// Mitsubishi GX Works2 project: 21.8电机点动互锁（复杂）   PLC: FX3U/FX3UC

PROGRAM MAIN
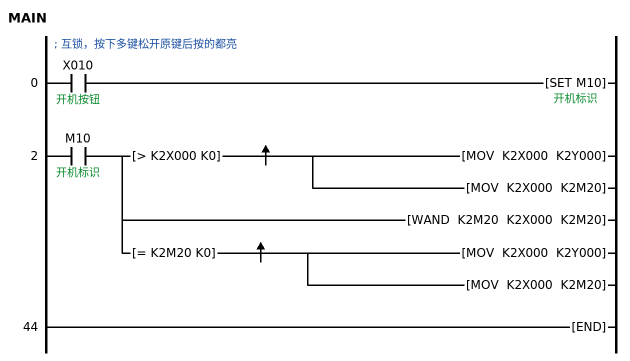
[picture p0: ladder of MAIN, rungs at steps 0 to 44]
; 互锁，按下多键松开原键后按的都亮
0     LD      X010  ; 开机按钮
      SET     M10  ; 开机标识
2     LD      M10  ; 开机标识
      MPS
      AND>    K2X000 K0  ; 启动按钮
      MEP
      MOV     K2X000 K2Y000  ; 电机
        [note] 按下K2X0时执行K2Y0
      MOV     K2X000 K2M20  ; 记录按键情况
        [note] 将K2X0按下的情况记录
      MPP
      WAND    K2M20 K2X000 K2M20
        [note] 按键与记录一致时更新电机状态
      AND=    K2M20 K0  ; 记录按键情况
      MEP
      MOV     K2X000 K2Y000
        [note] 更新未按键时电机状态
      MOV     K2X000 K2M20
        [note] 记录按键的状态
44    END
END_PROGRAM

// device comments not shown above
M0  ; 电机运行标识
